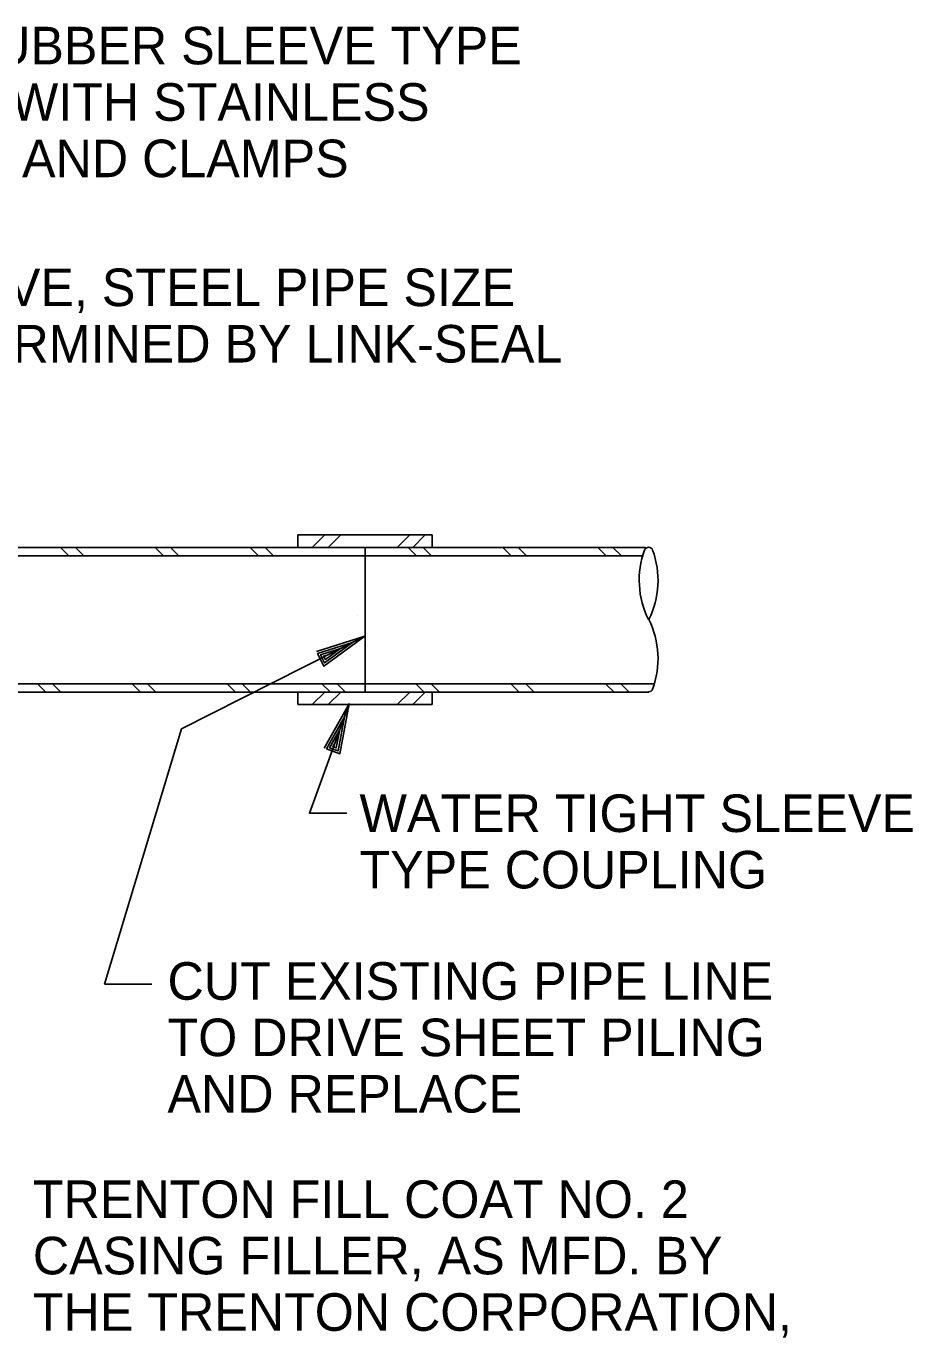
# Model space of a CAD drawing. Extents: x 22422.9 to 22498.9, y 22369.6 to 22415.
# Drawn here: x 22471.7 to 22476.1, y 22384.59 to 22391.11 of the extents above; entities that cross this region are included whole.
import ezdxf

# ---------------------------------------------------------------- set-up
doc = ezdxf.new("R2010")
doc.units = 0
for name, color, linetype in [('Level 1', 7, 'Continuous'), ('Level 2', 7, 'Continuous'), ('Level 4', 7, 'Continuous'), ('Level 8', 7, 'Continuous')]:
    doc.layers.add(name, color=color, linetype=linetype)

msp = doc.modelspace()

# ---------------------------------------------------------------- linework, layer by layer
at = {"layer": 'Level 1'}
for p, q in [((22473.3437, 22388.1757), (22473.3437, 22388.1757)), ((22473.3798, 22388.235), (22473.3798, 22388.235)), ((22473.369, 22387.6965), (22473.369, 22387.6965)), ((22473.3324, 22387.6375), (22473.3324, 22387.6375))]:
    msp.add_line(p, q, dxfattribs=at)
for centre, radius, start, end in [((22475.178, 22388.351), 0.4356, 159.80644, 206.60705), ((22474.7892, 22388.494), 0.0213, 20.19356, 159.80644), ((22474.4003, 22388.351), 0.4356, 333.39295, 20.19356), ((22474.4003, 22387.9608), 0.4356, 339.80812, 26.60705), ((22474.7892, 22387.8178), 0.0213, 270, 339.68454)]:
    msp.add_arc(centre, radius, start, end, dxfattribs=at)
at = {"layer": 'Level 2'}
for p, q in [((22473.0465, 22388.514), (22473.0465, 22388.5765)), ((22473.0465, 22388.5765), (22473.7131, 22388.5765)), ((22473.7131, 22388.514), (22473.7131, 22388.5765)), ((22468.1298, 22388.514), (22474.774, 22388.514)), ((22473.3798, 22387.7953), (22473.3798, 22388.514)), ((22468.1298, 22388.4724), (22474.7645, 22388.4724)), ((22472.4675, 22387.6126), (22473.3796, 22388.0732)), ((22468.1298, 22387.8369), (22474.813, 22387.8369)), ((22468.1298, 22387.7953), (22474.7895, 22387.7953)), ((22473.0465, 22387.7328), (22473.0465, 22387.7953)), ((22473.7131, 22387.7328), (22473.7131, 22387.7953)), ((22473.0465, 22387.7328), (22473.7131, 22387.7328)), ((22472.0852, 22386.3436), (22472.4675, 22387.6126)), ((22472.3199, 22386.3436), (22472.0852, 22386.3436))]:
    msp.add_line(p, q, dxfattribs=at)
for points in [[(22473.1384, 22387.9977), (22473.3796, 22388.0732), (22473.1757, 22387.9239), (22473.1438, 22387.987), (22473.3177, 22388.042), (22473.1792, 22387.9406), (22473.1587, 22387.9811), (22473.2582, 22388.0119), (22473.1827, 22387.9574), (22473.1743, 22387.974), (22473.1963, 22387.9807)], [(22473.289, 22387.1926), (22473.1037, 22387.1926), (22473.301, 22387.737)], [(22473.1772, 22387.5167), (22473.301, 22387.737), (22473.2549, 22387.4885), (22473.1885, 22387.5126), (22473.2774, 22387.6718), (22473.246, 22387.5031), (22473.2034, 22387.5185), (22473.2547, 22387.6091), (22473.2371, 22387.5176), (22473.2195, 22387.524), (22473.231, 22387.5439)]]:
    msp.add_lwpolyline(points, dxfattribs=at)
at = {"layer": 'Level 8'}
for p, q in [((22473.3796, 22388.0732), (22473.3796, 22388.0732)), ((22473.3177, 22388.042), (22473.3177, 22388.042)), ((22473.301, 22387.737), (22473.301, 22387.737)), ((22473.2774, 22387.6718), (22473.2774, 22387.6718))]:
    msp.add_line(p, q, dxfattribs=at)
for points in [[(22473.1798, 22388.5765), (22473.1173, 22388.514)], [(22473.2595, 22388.5765), (22473.197, 22388.514)], [(22473.6017, 22388.5765), (22473.5392, 22388.514)], [(22473.6793, 22388.5765), (22473.6168, 22388.514)], [(22471.9074, 22388.4724), (22471.8658, 22388.514)], [(22471.9828, 22388.4724), (22471.9412, 22388.514)], [(22472.3788, 22388.4724), (22472.3372, 22388.514)], [(22472.4542, 22388.4724), (22472.4126, 22388.514)], [(22472.8502, 22388.4724), (22472.8086, 22388.514)], [(22472.9257, 22388.4724), (22472.884, 22388.514)], [(22473.6353, 22388.4724), (22473.5937, 22388.514)], [(22473.7108, 22388.4724), (22473.6691, 22388.514)], [(22474.1067, 22388.4724), (22474.0651, 22388.514)], [(22474.1822, 22388.4724), (22474.1405, 22388.514)], [(22474.5782, 22388.4724), (22474.5365, 22388.514)], [(22474.6536, 22388.4724), (22474.6119, 22388.514)], [(22471.7933, 22387.7953), (22471.7516, 22387.8369)], [(22471.8687, 22387.7953), (22471.827, 22387.8369)], [(22472.2647, 22387.7953), (22472.223, 22387.8369)], [(22472.3401, 22387.7953), (22472.2984, 22387.8369)], [(22472.7361, 22387.7953), (22472.6944, 22387.8369)], [(22472.8115, 22387.7953), (22472.7698, 22387.8369)], [(22473.1798, 22387.7953), (22473.1173, 22387.7328)], [(22473.2075, 22387.7953), (22473.1658, 22387.8369)], [(22473.2595, 22387.7953), (22473.197, 22387.7328)], [(22473.2829, 22387.7953), (22473.2412, 22387.8369)], [(22473.6017, 22387.7953), (22473.5392, 22387.7328)], [(22473.6793, 22387.7953), (22473.6168, 22387.7328)], [(22473.6744, 22387.7953), (22473.6327, 22387.8369)], [(22473.7498, 22387.7953), (22473.7081, 22387.8369)], [(22474.1458, 22387.7953), (22474.1041, 22387.8369)], [(22474.2212, 22387.7953), (22474.1795, 22387.8369)], [(22474.6172, 22387.7953), (22474.5755, 22387.8369)], [(22474.6926, 22387.7953), (22474.6509, 22387.8369)]]:
    msp.add_lwpolyline(points, dxfattribs=at)

# ---------------------------------------------------------------- texts
at = {"layer": 'Level 4'}
for s, p in [('NEOPRENE RUBBER SLEEVE TYPE', (22469.8861, 22390.9156)), ('CASING SEAL WITH STAINLESS', (22469.8861, 22390.6351)), ('STEEL BANDS AND CLAMPS', (22469.8861, 22390.3547)), ('SLEEVE, STEEL PIPE SIZE', (22470.9621, 22389.7138)), ('DETERMINED BY LINK-SEAL', (22470.9621, 22389.4334)), ('WATER TIGHT SLEEVE', (22473.3524, 22387.0997)), ('TYPE COUPLING ', (22473.3524, 22386.8193)), ('CUT EXISTING PIPE LINE', (22472.3984, 22386.266)), ('TO DRIVE SHEET PILING', (22472.3984, 22385.9856)), ('AND REPLACE', (22472.3984, 22385.7052)), ('TRENTON FILL COAT NO. 2', (22471.7294, 22385.1814)), ('CASING FILLER, AS MFD. BY', (22471.7294, 22384.9009)), ('THE TRENTON CORPORATION,', (22471.7294, 22384.6205))]:
    msp.add_text(s, height=0.186667, dxfattribs=at).set_placement(p)

doc.saveas('drawing.dxf')
